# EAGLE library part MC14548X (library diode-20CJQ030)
Motorola's MC145481 3V PCM Codec-Filter and MC145483 13-bit linear PCM Codec-Filter The MC145481 is a general purpose per channel PCM Codec-Filter with pin selectable Mu-Law or A-Law companding, and is offered in 20-pin SOG and SSOP packages. This device performs the voice digitization and reconstruction as well as the band limiting and smoothing required for PCM systems. This device is designed to operate in both synchronous and asynchronous applications and contains an on-chip precision reference voltage. This device has an input operational amplifier whose output is the input to the encoder section. The encoder section immediately low-pass filters the analog signal with an active R-C filter to eliminate very high frequency noise from being modulated down to the passband by the switched capacitor filter. From the active R-C filter, the analog signal is converted to a differential signal. From this point, all analog signal processing is done differentially. This allows processing of an analog signal that is twice the amplitude allowed by a single-ended design, which reduces the significance of noise to both the inverted and non-inverted signal paths. Another advantage of this differential design is that noise injected via the power supplies is a common-mode signal that is cancelled when the inverted and non-inverted signals are recombined. This dramatically improves the power supply rejection ratio. After the differential converter, a differential switched capacitor filter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
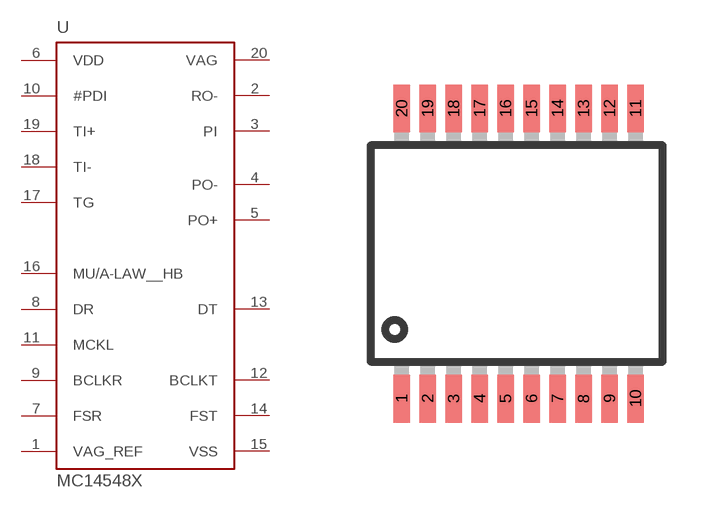
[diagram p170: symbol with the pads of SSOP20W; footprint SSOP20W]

Designator prefix U

## MC14548X-SD  [SSOP20W]
1  VAG_REF  in
2  RO-  out
3  PI  in
4  PO-  out
5  PO+  out
6  VDD  pwr
7  FSR  in
8  DR  in
9  BCLKR  in
10  #PDI  in
11  MCKL  in
12  BCLKT  out
13  DT  out
14  FST  out
15  VSS  pwr
16  MU/A-LAW__HB  in
17  TG  out
18  TI-  in
19  TI+  in
20  VAG  out

## Footprint SSOP20W (pad centres in mm)
smd 0.42 x 1.2: 1 -2.925,-3.625; 2 -2.275,-3.625; 3 -1.625,-3.625; 4 -0.975,-3.625; 5 -0.325,-3.625; 6 0.325,-3.625; 7 0.975,-3.625; 8 1.625,-3.625; 9 2.275,-3.625; 10 2.925,-3.625; 11 2.925,3.625; 12 2.275,3.625; 13 1.625,3.625; 14 0.975,3.625; 15 0.325,3.625; 16 -0.325,3.625; 17 -0.975,3.625; 18 -1.625,3.625; 19 -2.275,3.625; 20 -2.925,3.625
